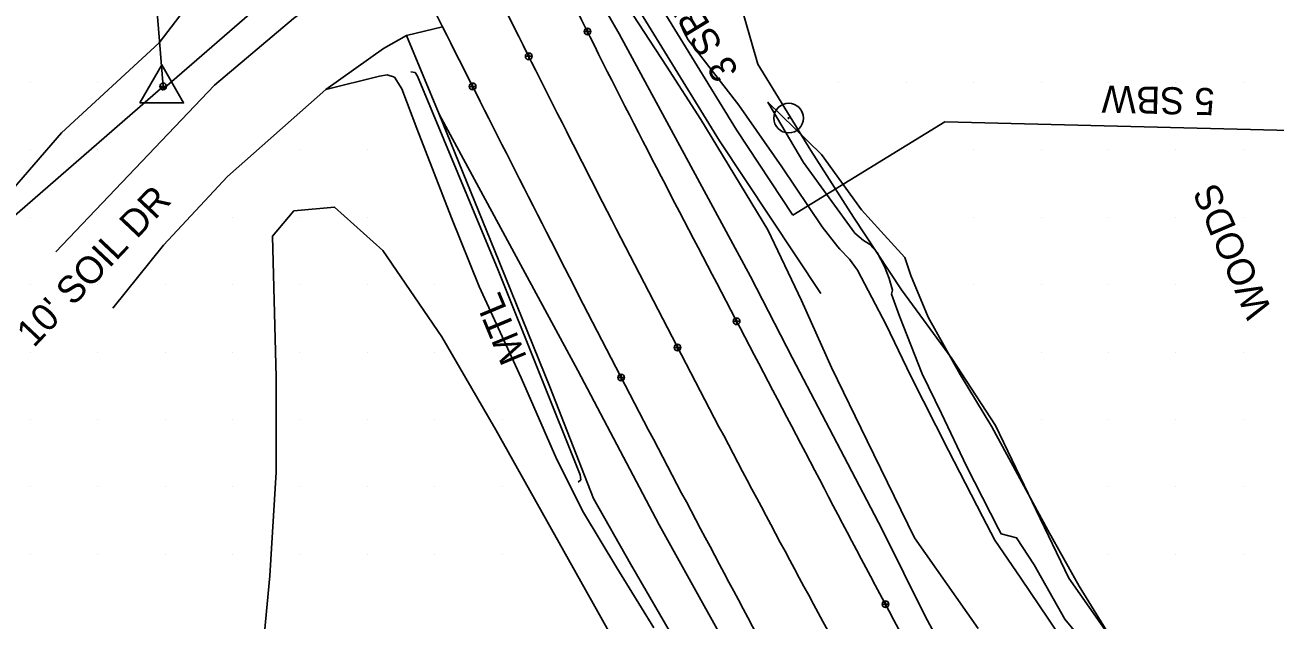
# Model space of a CAD drawing. Extents: x 1548934 to 1561348, y 809680 to 824075.
# Drawn here: x 1551839.2 to 1552024.7, y 810460.2 to 810548.5 of the extents above; entities that cross this region are included whole.
import ezdxf

# ---------------------------------------------------------------- set-up
doc = ezdxf.new("R2010")
doc.units = 0
for name, color, linetype in [('Default', 7, 'Continuous'), ('E_NCDOT_Vertical_Profile_Ground_Line', 7, 'Continuous'), ('Exist DTM QL2 LIDAR Elevation Point', 7, 'Continuous'), ('Exist Guardrail', 7, 'Continuous'), ('Exist Guardrail Text', 7, 'Continuous'), ('Exist Other Culture Fence Line Text', 7, 'Continuous'), ('Exist Right of Way Control of Access CA Symbol CELL', 7, 'Continuous'), ('Exist Roads Soil', 7, 'Continuous'), ('Exist Roads Soil Text', 7, 'Continuous'), ('Exist Vegetation Woods Line', 7, 'Continuous'), ('Exist Vegetation Woods Line Text', 7, 'Continuous'), ('P_NCDOT_Horizontal_Alignment_Tick_Large', 7, 'Continuous'), ('P_NCDOT_Vertical_Profile_Grade_Minor_Road', 7, 'Continuous'), ('P_RDY_Dimension_Text', 7, 'Continuous'), ('PH Exist DTM Breakline', 7, 'Continuous')]:
    doc.layers.add(name, color=color, linetype=linetype)

# ---------------------------------------------------------------- blocks, each defined once
blk = doc.blocks.new('SurveyPointCell')
at = {"layer": 'Default'}
for p, q in [((-0.5, 0), (0.5, 0)), ((0, -0.5), (0, 0.5))]:
    blk.add_line(p, q, dxfattribs=at)
blk.add_circle((0, 0), 0.5, dxfattribs=at)

msp = doc.modelspace()

# ---------------------------------------------------------------- linework, layer by layer
at = {"layer": 'E_NCDOT_Vertical_Profile_Ground_Line'}
msp.add_line((1551859.49, 810538.84), (1551859.49, 810538.84), dxfattribs=at)
msp.add_lwpolyline([(1551856.25, 810536.95), (1551859.49, 810542.59), (1551862.74, 810536.95)], close=True, dxfattribs=at)
for points in [[(1552269.12, 810011.85), (1552259.92, 810023.16), (1552240.77, 810045.39), (1552214.34, 810080.42), (1552187.87, 810115.32), (1552162.13, 810150.99), (1552135.64, 810187.58), (1552109.72, 810225.45), (1552084.15, 810264.06), (1552058.91, 810303.06), (1552035.06, 810342.6), (1552011.64, 810381.93), (1551989.04, 810421.64), (1551966.75, 810462.54), (1551944.7, 810504.81), (1551922.38, 810547.42), (1551904.22, 810585.98), (1551891.94, 810609.51), (1551888.01, 810619.12)], [(1552253.41, 809998.89), (1552244.07, 810010.35), (1552226, 810034.01), (1552199.08, 810069.05), (1552172.73, 810104.35), (1552146.5, 810139.67), (1552120.17, 810176.34), (1552094.24, 810214.53), (1552068.08, 810253.47), (1552042.84, 810293.18), (1552018.16, 810332.72), (1551995.31, 810372.57), (1551972.35, 810412.52), (1551950.07, 810453.78), (1551927.46, 810496.24), (1551905.62, 810539.48), (1551886.94, 810576.33), (1551876.35, 810599.17), (1551872.14, 810607.03)]]:
    msp.add_open_spline(points, degree=3, dxfattribs=at)
at = {"layer": 'Exist DTM QL2 LIDAR Elevation Point'}
for p, q in [((1551840.01, 810539.97), (1551840.01, 810539.97)), ((1551850.01, 810539.97), (1551850.01, 810539.97)), ((1551860.01, 810539.97), (1551860.01, 810539.97)), ((1551960.02, 810539.97), (1551960.02, 810539.97)), ((1551970.02, 810539.97), (1551970.02, 810539.97)), ((1551980.02, 810539.97), (1551980.02, 810539.97)), ((1551990.02, 810539.97), (1551990.02, 810539.97)), ((1552000.02, 810539.97), (1552000.02, 810539.97)), ((1552010.02, 810539.97), (1552010.02, 810539.97)), ((1552020.02, 810539.97), (1552020.02, 810539.97)), ((1551840.01, 810529.97), (1551840.01, 810529.97)), ((1551850.01, 810529.97), (1551850.01, 810529.97)), ((1551880.01, 810529.97), (1551880.01, 810529.97)), ((1551890.01, 810529.97), (1551890.01, 810529.97)), ((1551970.02, 810529.97), (1551970.02, 810529.97)), ((1551980.02, 810529.97), (1551980.02, 810529.97)), ((1551990.02, 810529.97), (1551990.02, 810529.97)), ((1552000.02, 810529.97), (1552000.02, 810529.97)), ((1552010.02, 810529.97), (1552010.02, 810529.97)), ((1552020.02, 810529.97), (1552020.02, 810529.97)), ((1551840.01, 810519.97), (1551840.01, 810519.97)), ((1551870.01, 810519.97), (1551870.01, 810519.97)), ((1551880.01, 810519.97), (1551880.01, 810519.97)), ((1551890.01, 810519.97), (1551890.01, 810519.97)), ((1551980.02, 810519.97), (1551980.02, 810519.97)), ((1551990.02, 810519.97), (1551990.02, 810519.97)), ((1552000.02, 810519.97), (1552000.02, 810519.97)), ((1552010.02, 810519.97), (1552010.02, 810519.97)), ((1552020.02, 810519.97), (1552020.02, 810519.97)), ((1551840.01, 810509.97), (1551840.01, 810509.97)), ((1551850.01, 810509.97), (1551850.01, 810509.97)), ((1551860.01, 810509.97), (1551860.01, 810509.97)), ((1551870.01, 810509.97), (1551870.01, 810509.97)), ((1551880.01, 810509.97), (1551880.01, 810509.97)), ((1551890.01, 810509.97), (1551890.01, 810509.97)), ((1551900.01, 810509.97), (1551900.01, 810509.97)), ((1551980.02, 810509.97), (1551980.02, 810509.97)), ((1551990.02, 810509.97), (1551990.02, 810509.97)), ((1552000.02, 810509.97), (1552000.02, 810509.97)), ((1552010.02, 810509.97), (1552010.02, 810509.97)), ((1552020.02, 810509.97), (1552020.02, 810509.97)), ((1551840.01, 810499.97), (1551840.01, 810499.97)), ((1551850.01, 810499.97), (1551850.01, 810499.97)), ((1551860.01, 810499.97), (1551860.01, 810499.97)), ((1551870.01, 810499.97), (1551870.01, 810499.97)), ((1551880.01, 810499.97), (1551880.01, 810499.97)), ((1551890.01, 810499.97), (1551890.01, 810499.97)), ((1551900.01, 810499.97), (1551900.01, 810499.97)), ((1551990.02, 810499.97), (1551990.02, 810499.97)), ((1552000.02, 810499.97), (1552000.02, 810499.97)), ((1552010.02, 810499.97), (1552010.02, 810499.97)), ((1552020.02, 810499.97), (1552020.02, 810499.97)), ((1551840.01, 810489.97), (1551840.01, 810489.97)), ((1551850.01, 810489.97), (1551850.01, 810489.97)), ((1551860.01, 810489.97), (1551860.01, 810489.97)), ((1551870.01, 810489.97), (1551870.01, 810489.97)), ((1551880.01, 810489.97), (1551880.01, 810489.97)), ((1551890.01, 810489.97), (1551890.01, 810489.97)), ((1551900.01, 810489.97), (1551900.01, 810489.97)), ((1551910.01, 810489.97), (1551910.01, 810489.97)), ((1551990.02, 810489.97), (1551990.02, 810489.97)), ((1552000.02, 810489.97), (1552000.02, 810489.97)), ((1552010.02, 810489.97), (1552010.02, 810489.97)), ((1552020.02, 810489.97), (1552020.02, 810489.97)), ((1551840.01, 810479.97), (1551840.01, 810479.97)), ((1551850.01, 810479.97), (1551850.01, 810479.97)), ((1551860.01, 810479.97), (1551860.01, 810479.97)), ((1551870.01, 810479.97), (1551870.01, 810479.97)), ((1551880.01, 810479.97), (1551880.01, 810479.97)), ((1551890.01, 810479.97), (1551890.01, 810479.97)), ((1551900.01, 810479.97), (1551900.01, 810479.97)), ((1551910.01, 810479.97), (1551910.01, 810479.97)), ((1552000.02, 810479.97), (1552000.02, 810479.97)), ((1552010.02, 810479.97), (1552010.02, 810479.97)), ((1552020.02, 810479.97), (1552020.02, 810479.97)), ((1551840.01, 810469.97), (1551840.01, 810469.97)), ((1551850.01, 810469.97), (1551850.01, 810469.97)), ((1551860.01, 810469.97), (1551860.01, 810469.97)), ((1551870.01, 810469.97), (1551870.01, 810469.97)), ((1551880.01, 810469.97), (1551880.01, 810469.97)), ((1551890.01, 810469.97), (1551890.01, 810469.97)), ((1551900.01, 810469.97), (1551900.01, 810469.97)), ((1551910.01, 810469.97), (1551910.01, 810469.97)), ((1552000.02, 810469.97), (1552000.02, 810469.97)), ((1552010.02, 810469.97), (1552010.02, 810469.97)), ((1552020.02, 810469.97), (1552020.02, 810469.97))]:
    msp.add_line(p, q, dxfattribs=at)
at = {"layer": 'Exist Guardrail'}
for points in [[(1551911.14, 810585.78), (1551911.04, 810584.73), (1551911.5, 810584.16), (1551924.39, 810560.5), (1551942.29, 810531.33), (1551957.31, 810508.64)], [(1551921.29, 810480.63), (1551921.69, 810480.98), (1551921.58, 810481.73), (1551909.43, 810512.1), (1551897.44, 810540.95), (1551897.1, 810541.46), (1551896.49, 810541.56)]]:
    msp.add_lwpolyline(points, dxfattribs=at)
at = {"layer": 'Exist Right of Way Control of Access CA Symbol CELL'}
msp.add_line((1551859.5, 810538.83), (1551938.35, 810607.43), dxfattribs=at)
at = {"layer": 'Exist Roads Soil'}
for points in [[(1551843.79, 810514.87), (1551867.35, 810539.6), (1551879.03, 810549.49), (1551884.67, 810553.81), (1551889.75, 810558.34), (1551893.1, 810564.33)], [(1551901.16, 810548.27), (1551895.83, 810546.97), (1551892.4, 810545.05), (1551883.84, 810538.93), (1551869.25, 810526.05), (1551859.78, 810515.83), (1551852.22, 810506.5)]]:
    msp.add_lwpolyline(points, dxfattribs=at)
at = {"layer": 'Exist Vegetation Woods Line'}
for points in [[(1551834.42, 810597.57), (1551843.72, 810589.97), (1551845.29, 810586.54), (1551854, 810584.96), (1551859.53, 810577.74), (1551862.79, 810570.06), (1551866.81, 810560.74), (1551865.25, 810553.94), (1551859.11, 810545.86), (1551844.62, 810532.53), (1551836.39, 810523.01)], [(1552000.15, 810457.78), (1551994.13, 810466.38), (1551983.27, 810489.04), (1551976.76, 810499.03), (1551969.31, 810509.21), (1551962.16, 810520.01), (1551955.86, 810529.9), (1551947.99, 810542.71), (1551945.04, 810552.93), (1551946.97, 810562.11), (1551954.24, 810567.48), (1551964.31, 810567.95), (1551974.4, 810564.45), (1551981.49, 810561.6), (1551992.68, 810562.81), (1552005.38, 810565.61), (1552015.11, 810567.52), (1552026.47, 810567.76)], [(1551874.19, 810452.55), (1551875.55, 810466.74), (1551876.47, 810482.15), (1551876.48, 810496.21), (1551875.94, 810517.17), (1551879.12, 810520.91), (1551885.15, 810521.5), (1551892.31, 810515.04), (1551901.05, 810502.2), (1551909.09, 810488.42), (1551948.76, 810417.59)]]:
    msp.add_lwpolyline(points, dxfattribs=at)
at = {"layer": 'P_NCDOT_Horizontal_Alignment_Tick_Large'}
for centre, radius in [((1551952.55, 810534.7), 2.2), ((1551952.55, 810534.71), 2.2), ((1551952.55, 810534.7), 0.0707), ((1551952.55, 810534.71), 0.0707)]:
    msp.add_circle(centre, radius, dxfattribs=at)
at = {"layer": 'P_NCDOT_Vertical_Profile_Grade_Minor_Road'}
msp.add_open_spline([(1551879.82, 810614.21), (1551884.04, 810605.38), (1551895.16, 810581.81), (1551913.82, 810543.91), (1551935.87, 810500.72), (1551958.31, 810458.4), (1551980.95, 810417.47), (1552003.45, 810377.53), (1552026.54, 810337.94), (1552050.88, 810298.39), (1552075.93, 810258.79), (1552101.83, 810219.9), (1552127.9, 810181.92), (1552154.01, 810145.19), (1552180.07, 810109.84), (1552206.52, 810074.71), (1552233.37, 810039.85), (1552251.61, 810016.53), (1552260.84, 810005.28)], degree=3, dxfattribs=at)
at = {"layer": 'P_RDY_Dimension_Text'}
msp.add_line((1551975.71, 810534.13), (1552061.55, 810532.04), dxfattribs=at)
for points in [[(1551861.69, 810604.33), (1551854.9, 810598.77), (1551859.71, 810539.41)], [(1551928.06, 810560.25), (1551944.82, 810532.95), (1551953.19, 810520.3)], [(1551859.71, 810539.41), (1551760.08, 810452.75), (1551665.88, 810372.94), (1551515.48, 810250.92)], [(1551953.19, 810520.3), (1551975.71, 810534.13)]]:
    msp.add_lwpolyline(points, dxfattribs=at)
at = {"layer": 'PH Exist DTM Breakline'}
for points in [[(1552016.73, 810408.79), (1552015.13, 810407.56), (1552013.21, 810406.75), (1552011.38, 810406.7), (1552007.71, 810407.24), (1552004.35, 810408.79), (1552001.51, 810411.37), (1551998.56, 810416.12), (1551995.48, 810420.58), (1551991.92, 810426.01), (1551985.21, 810437.97), (1551979.72, 810447.97), (1551972.87, 810460.66), (1551966.45, 810473.62), (1551960.8, 810484.4), (1551953.12, 810499.06), (1551946.88, 810511.19), (1551938.04, 810527.59), (1551927.38, 810547.23), (1551920.41, 810559.38), (1551911.29, 810577.6)], [(1551980.68, 810458.9), (1551971.25, 810472.4), (1551964.22, 810486.8), (1551958.9, 810497.69), (1551954.46, 810507.63), (1551949.47, 810518.09), (1551939.53, 810534.51), (1551934.42, 810542.42), (1551928.61, 810551.29)], [(1551936.45, 810548.79), (1551937.03, 810547.43), (1551937.64, 810546.35), (1551945.15, 810536.6), (1551951.56, 810527.45), (1551957.52, 810518.54), (1551959.86, 810515.61), (1551960.13, 810515.26), (1551961.56, 810513.75), (1551962.77, 810512.12), (1551967, 810504.03), (1551970.68, 810496.37), (1551976.27, 810485.36), (1551981.34, 810475.55), (1551983.13, 810472.02), (1551987.03, 810466.37), (1551991.13, 810460.3), (1551995.49, 810453.73)], [(1551935.71, 810457.1), (1551929.06, 810468.5), (1551923.6, 810478.23), (1551917.09, 810494.81), (1551908.89, 810515.08), (1551900.66, 810535.28), (1551895.83, 810546.97)], [(1551932.56, 810459.02), (1551927.03, 810467.91), (1551922.11, 810476.16), (1551918.13, 810484.03), (1551912.85, 810496.16), (1551906.61, 810509.68), (1551902.5, 810519.87), (1551897.37, 810533.16), (1551895.11, 810539.05), (1551894.02, 810540.78), (1551892.95, 810541.11), (1551891.83, 810540.95), (1551883.84, 810538.93)], [(1552021.4, 810422.47), (1552018.91, 810426.43), (1552016.45, 810431.83), (1552009.84, 810444.31), (1552004.62, 810451.89), (1552000.39, 810457.56), (1551995.69, 810465.21), (1551991.04, 810473.54), (1551987.18, 810480.66), (1551982.7, 810488.86), (1551978.01, 810496.64), (1551973.24, 810505.16), (1551970.68, 810511.31), (1551969.79, 810513.98), (1551966.23, 810517.92), (1551963.37, 810521.08), (1551957.44, 810529.31), (1551949.48, 810537.06), (1551954.73, 810528.13)], [(1551900.66, 810535.28), (1551921.25, 810497.2), (1551933.34, 810474.29), (1551947.61, 810448.55), (1551960.63, 810425.09), (1551971.32, 810406.71), (1551989.65, 810374.75), (1552011.76, 810338.01), (1552027.69, 810311.76), (1552035.63, 810297.77), (1552036.31, 810295.88), (1552036.56, 810293.53), (1552036.06, 810290.99), (1552035.15, 810285.03)], [(1551998.22, 810454.62), (1551993.55, 810460.31), (1551989.01, 810468.37), (1551986.37, 810472.37), (1551984.1, 810472.95), (1551983.7, 810473.7), (1551978.95, 810483), (1551975.26, 810490.83), (1551972.38, 810496.75), (1551968.98, 810505.27), (1551967.8, 810508.58), (1551967.96, 810509.13), (1551967.47, 810510.88), (1551966.79, 810512.66), (1551965.68, 810514.77), (1551964.53, 810515.98), (1551964.13, 810516.24), (1551963.67, 810516.52), (1551962.37, 810517.63), (1551954.73, 810528.13)]]:
    msp.add_lwpolyline(points, dxfattribs=at)

# ---------------------------------------------------------------- block references
at = {"layer": 'Default'}
for p in [(1551922.7, 810547.56), (1551913.97, 810543.88), (1551859.71, 810539.41), (1551905.64, 810539.41), (1551944.82, 810504.54), (1551936.05, 810500.64), (1551927.68, 810496.19), (1551966.92, 810462.52)]:
    msp.add_blockref('SurveyPointCell', p, dxfattribs=at)

# ---------------------------------------------------------------- texts
at = {"layer": 'Exist Guardrail Text'}
msp.add_text('MTL', height=4.02, rotation=112.5582, dxfattribs=at).set_placement((1551913.75, 810499.18))
at = {"layer": 'Exist Other Culture Fence Line Text'}
for s, rotation, p in [('3 SBW', 121.551, (1551945.24, 810541.72)), ('5 SBW', 178.6044, (1552015.82, 810539.14))]:
    msp.add_text(s, height=4.02, rotation=rotation, dxfattribs=at).set_placement(p)
at = {"layer": 'Exist Roads Soil Text'}
msp.add_text("10' SOIL DR", height=4.02, rotation=46.5915, dxfattribs=at).set_placement((1551840.5, 810500.5))
at = {"layer": 'Exist Vegetation Woods Line Text'}
msp.add_text('WOODS', height=4.02, rotation=113.1736, dxfattribs=at).set_placement((1552024.36, 810506.08))

doc.saveas('drawing.dxf')
